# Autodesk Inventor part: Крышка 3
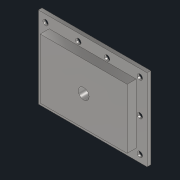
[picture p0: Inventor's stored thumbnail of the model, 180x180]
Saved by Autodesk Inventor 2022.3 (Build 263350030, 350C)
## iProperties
Created: 2022-08
Part Number: Крышка 3
Material: Сталь 45ХНМА
Document SubType Name: Modeling
Designer: Карташов
Density: 7.85 g/cm^3
Appearance: С умеренной полировкой
Author: Карташов
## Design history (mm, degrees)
sketch "Эскиз1"
  geometry: L1 (-60, -45)-(60, -45); L2 (60, -45)-(60, 45); L3 (60, 45)-(-60, 45); L4 (-60, 45)-(-60, -45); L5 (-60, -45)-(60, 45); L6 (60, -45)-(-60, 45); L7 (-2.653, 0)-(0, 0); L8 (0, 3.174)-(0, 0); C1 r 6 at (0, 0); 12 further points
  constraints: 16 end point, 6 symmetric about line, 5 midpoint, 3 horizontal alignment, 2 horizontal, 2 parallel, 2 perpendicular, 2 vertical alignment, 1 centre point
  dimensions: "d0" = 120 distance of L3.end L2.end; "d1" = 90 distance of L2.end L1.end; "d2" = 12 diameter of C1; "d3" = 37 vertical distance of point (-52, 37) L7.end; "d4" = 52 horizontal distance of L7.end point (-52, 37); "d5" = 15.835 horizontal distance of point (-15.835, 37) L7.end
extrude "Выдавливание1" new body sketch "Эскиз1" distance "d6" = 14; taper "d7" = 0 deg
sketch "Эскиз2"
  geometry: L1 (60, -45)-(60, 45) reference; L2 (60, 45)-(-60, 45) reference; L3 (-60, 45)-(-60, -45) reference; L4 (-60, -45)-(60, -45) reference; L5 (48, -33)-(-48, -33); L6 (-48, -33)-(-48, 33); L7 (-48, 33)-(48, 33); L8 (48, 33)-(48, -33); L9 (48, -33)-(-48, 33); L10 (-48, -33)-(48, 33); C1 r 6 at (0, 0) reference; 1 further point
  constraints: 12 end point, 2 midpoint, 2 parallel, 1 horizontal, 1 perpendicular
  dimensions: "d8" = 96 distance of L6.end L7.end; "d9" = 66 distance of L5.end L6.end
extrude "Выдавливание2" cut sketch "Эскиз2" distance "d10" = 10; taper "d11" = 0 deg
hole "Отверстие1" sketch "Эскиз1" diameter "d12" = 6; stored, may be unused: countersink angle "d16" = 90 deg, drill point angle "d18" = 0 deg; dims "d13" = 6, "d14" = 10, "d15" = 2, "d17" = 22.5
node "Твердое тело1"
node "Спроецированная петля1"
